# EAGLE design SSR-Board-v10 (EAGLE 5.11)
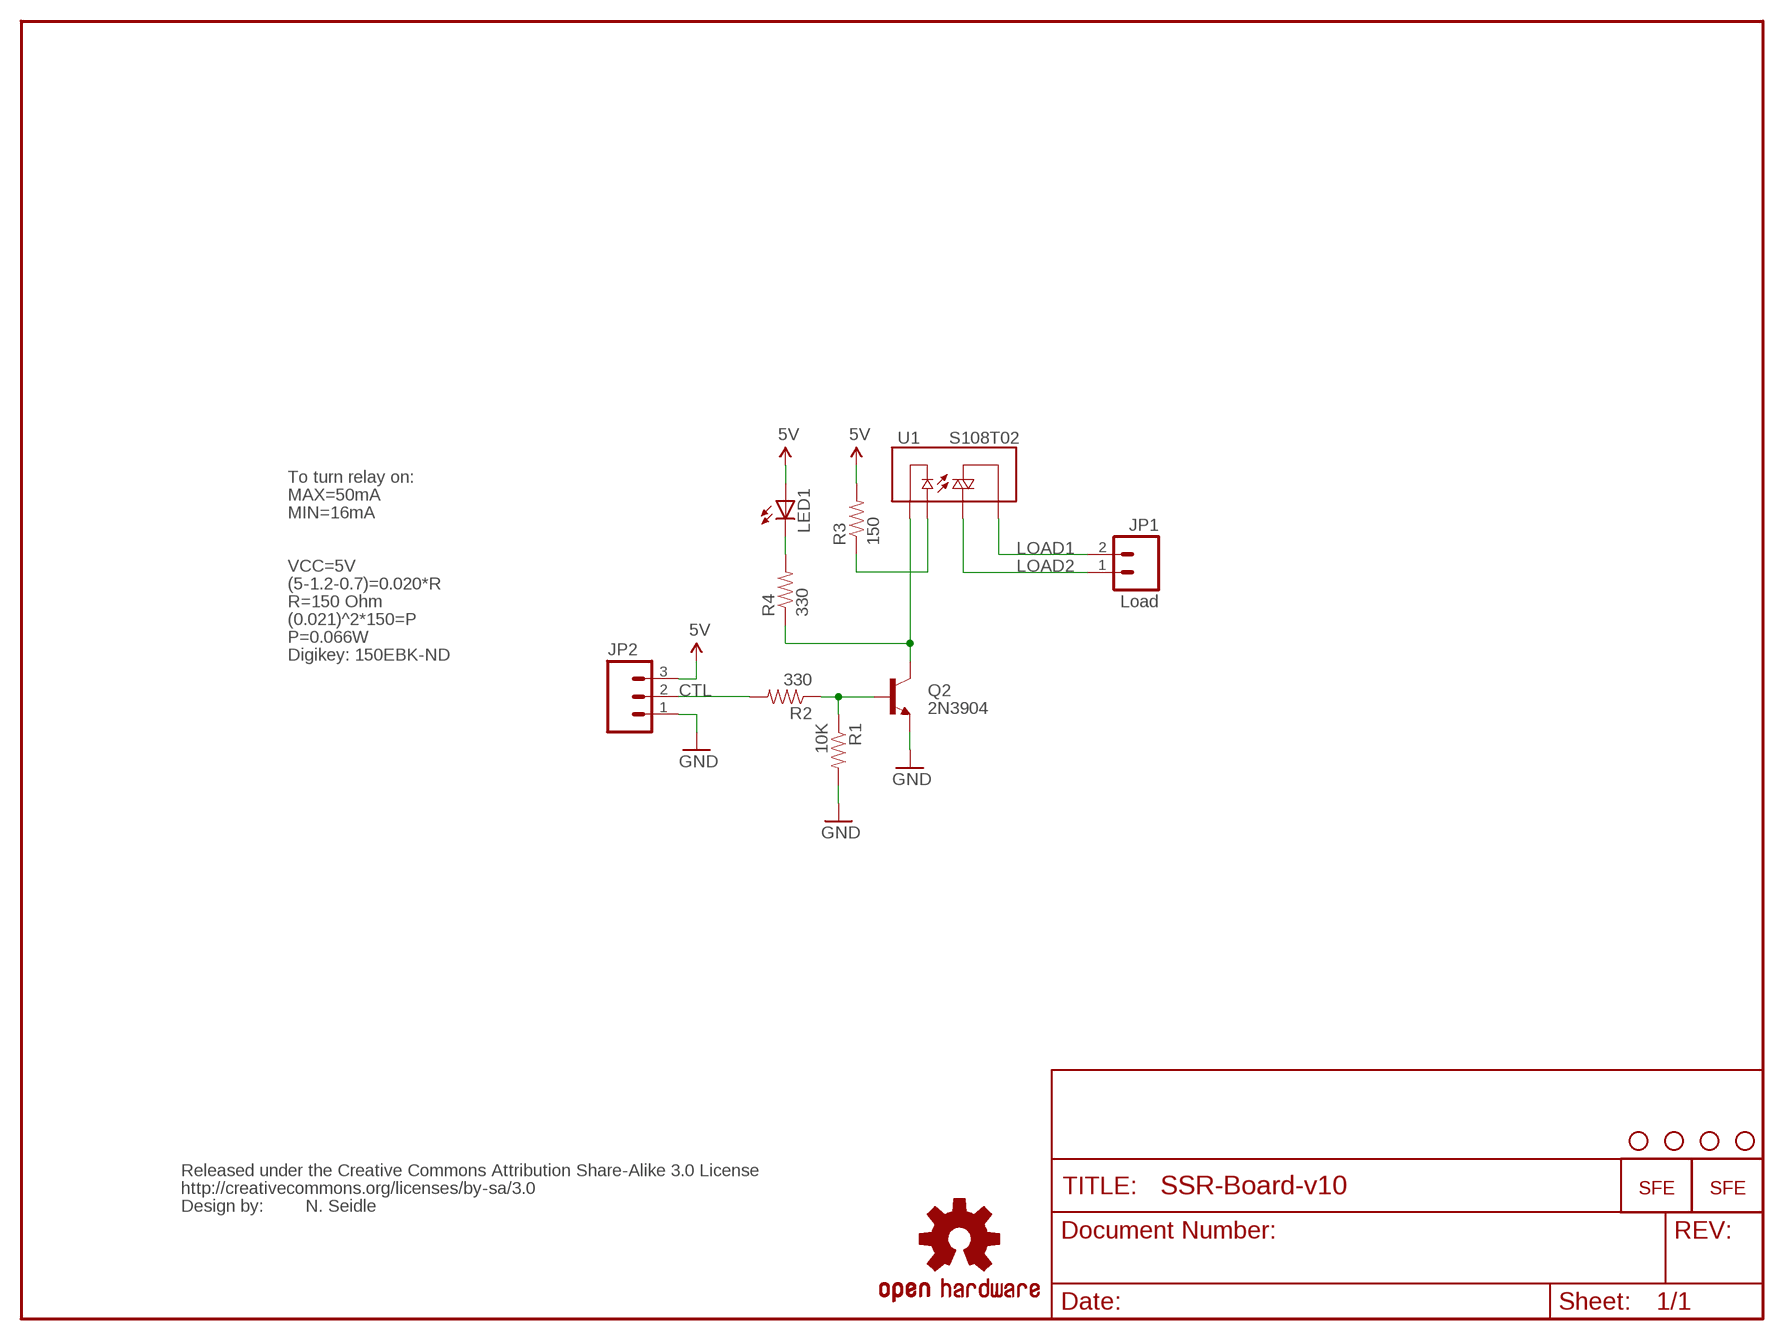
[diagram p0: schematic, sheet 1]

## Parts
JP1  Load  M025MM  [SCREWTERMINAL-5MM-2]
JP2  M03SCREW  [SCREWTERMINAL-3.5MM-3]
JP3  LOGO-SFESK  [SFE-LOGO-FLAME]
LED1  LED5MM  [LED5MM]
Q2  2N3904  TRANSISTOR_NPNTO92  [TO-92]
R1  10K  RESISTORAXIAL-0.3  [AXIAL-0.3]
R2  330  RESISTORAXIAL-0.3  [AXIAL-0.3]
R3  150  RESISTORAXIAL-0.3  [AXIAL-0.3]
R4  330  RESISTORAXIAL-0.3  [AXIAL-0.3]
U1  S108T02  RELAY-SOLIDSTATEPTH  [RELAY-S108T02]
U$1  LOGO-SFENEW  [SFE-NEW-WEBLOGO]
U$2  OSHW-LOGO  OSHW-LOGOS  [OSHW-LOGO-S]
U$3  STAND-OFF  [STAND-OFF]
U$4  STAND-OFF  [STAND-OFF]
U$5  STAND-OFF  [STAND-OFF]
U$7  STAND-OFF  [STAND-OFF]
U$9  CREATIVE_COMMONS  [CREATIVE_COMMONS]

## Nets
5V: JP2.3 LED1.A R3.P$2
COIL: Q2.3(C) R4.P$1 U1.4(-)
CTL: JP2.2 R2.P$2
GND: JP2.1 Q2.1(E) R1.P$2
LOAD1: JP1.2 U1.1(T1)
LOAD2: JP1.1 U1.2(T2)
N$1: R3.P$1 U1.3(+)
N$6: Q2.2(B) R1.P$1 R2.P$1
N$9: LED1.K(C) R4.P$2

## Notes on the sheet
- To turn relay on:
- MAX=50mA
- MIN=16mA
- VCC=5V
- (5-1.2-0.7)=0.020*R
- R=150 Ohm
- (0.021)^2*150=P
- P=0.066W
- Digikey: 150EBK-ND
- N. Seidle

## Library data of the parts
JP1 = SparkFun:M02: Header 2
JP2 = SparkFun:M03: Header 3 Standard 3-pin 0.1" header. Use with straight break away headers (SKU : PRT-00116), right angle break away headers (PRT-00553), swiss pins (PRT-00743), machine pins (PRT-00117), and female headers (PRT-00115). Molex polarized connector foot print use with SKU : PRT-08232 with associated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
JP3 U$1 = SparkFun:LOGO-SFE: Spark Fun Electronics PCB Logo
LED1 = SparkFun:LED: LEDs
Q2 = SparkFun:TRANSISTOR_NPN: Transistor NPN BJT configuration in SOT23 package. MMBT2222 is the common NPN we use. Double check BCE configuration again layout.
R1-R4 = SparkFun:RESISTOR: Resistor
U1 = SparkFun:RELAY-SOLIDSTATE
U$2 = SparkFun:OSHW-LOGO: Open Source Hardware Logo This logo indicates the piece of hardware it is found on incorporates a OSHW license and/or adheres to the definition of open source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
U$3-U$5 U$7 = SparkFun:STAND-OFF: Stand Off
U$9 = SparkFun:CREATIVE_COMMONS

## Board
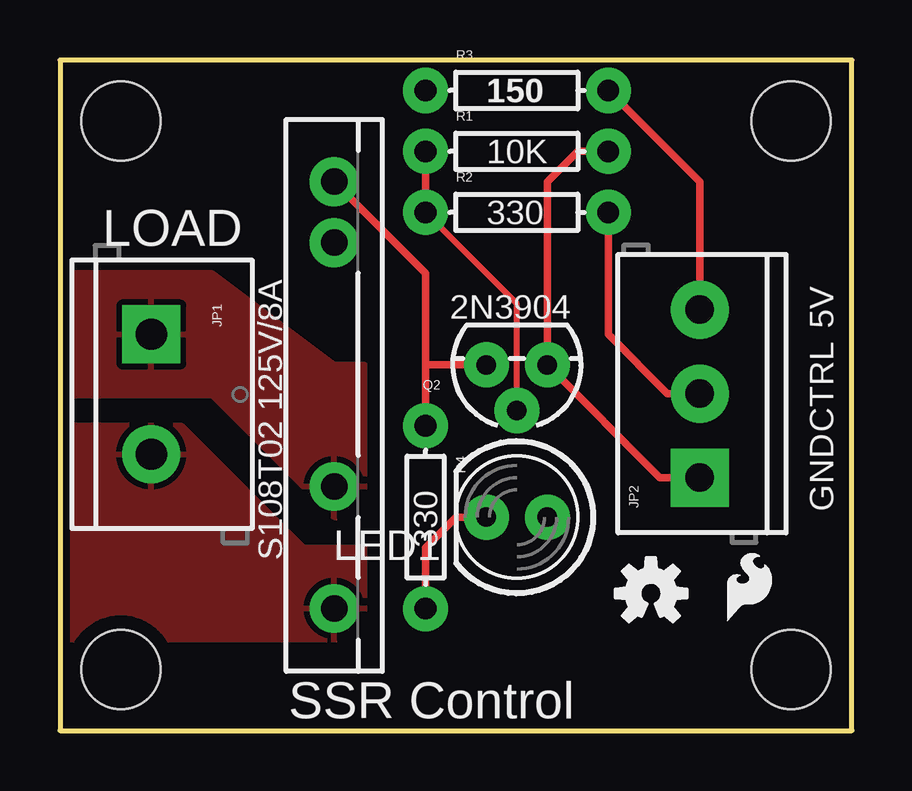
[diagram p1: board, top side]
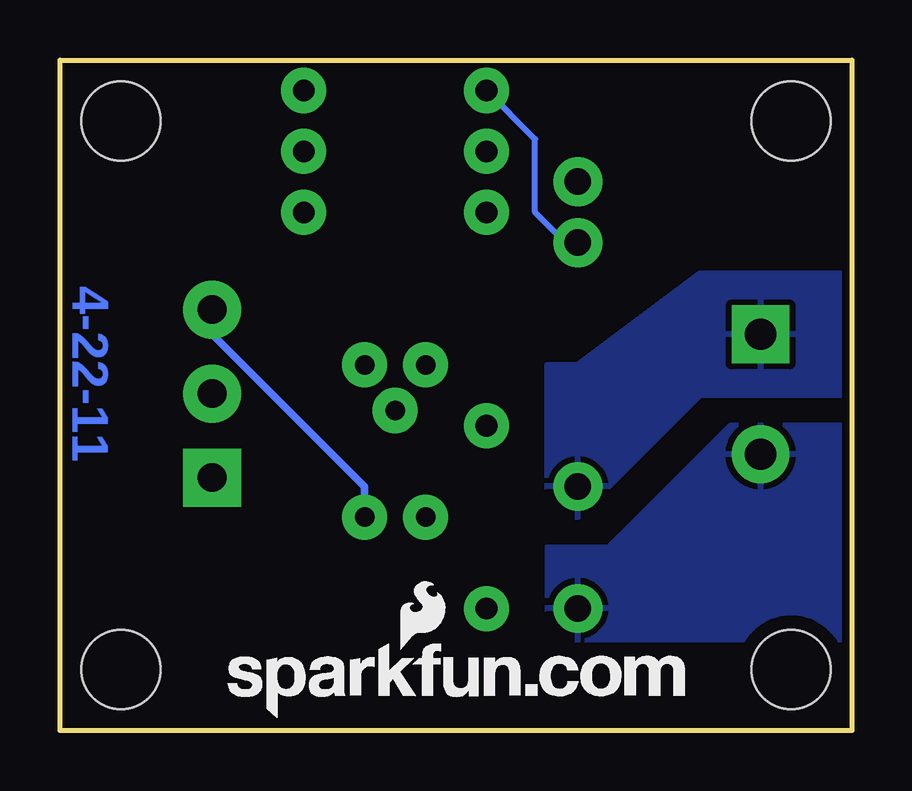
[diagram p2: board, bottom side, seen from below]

Size 33.02 x 27.94 mm. Coordinates in mm from the lower left corner, seen from the top.
Outline: 0,0 33.02,0 33.02,27.94 0,27.94 0,0
Copper layers (1*16): Top 0.035mm / dielectric 1.5mm / Bottom 0.035mm
Design rules "SparkFun *": minimum track width 10mil, minimum drill 20mil, track to track 8mil, track to pad 8mil, pad to pad 8mil, via to via 8mil, smd to smd 8mil, copper to edge 10mil, drill to drill 8mil, minimum pad ring 12mil, minimum via ring 10mil, stop-mask expansion 4mil, vias tented up to drill 20mil, thermal gap 10mil

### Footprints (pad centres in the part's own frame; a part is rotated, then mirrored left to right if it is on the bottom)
SCREWTERMINAL-5MM-2 = drill 1.3 pad 2.413 square: 1 0,0 | drill 1.3 pad 2.413 round: 2 5,0
SCREWTERMINAL-3.5MM-3 = drill 1.2 pad 2.413 square: 1 0,0 | drill 1.2 pad 2.413 round: 2 3.5,0; 3 7,0
LED5MM = drill 0.813 pad 1.88 round: A -1.27,0; K 1.27,0
TO-92 = drill 0.813 pad 1.88 round: 1 -1.27,0; 2 0,1.905; 3 1.27,0
AXIAL-0.3 = drill 0.9 pad 1.88 round: P$1 -3.81,0; P$2 3.81,0
RELAY-S108T02 = drill 1.1 pad 2.032 round: 1 -8.88,0; 2 -3.8,0; 3 6.36,0; 4 8.9,0
STAND-OFF = hole 3.302: 0,0

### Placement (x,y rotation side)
JP1  3.81,16.51 270 top
JP2  26.67,10.54 90 top
JP3  27.81,4.57 0 top
LED1  19.05,8.89 180 top
Q2  19.05,15.24 180 top
R1  19.05,24.13 0 top
R2  19.05,21.59 0 top
R3  19.05,26.67 0 top
R4  15.24,8.89 270 top
U1  11.43,13.97 90 top
U$1  26.04,0.51 0 bottom
U$2  24.64,5.71 0 top
U$3  2.54,2.54 0 top
U$4  30.48,2.54 0 top
U$5  30.48,25.4 0 top
U$7  2.54,25.4 0 top
U$9  not placed on the board

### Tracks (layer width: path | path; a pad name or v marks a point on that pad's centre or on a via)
5V
  Top 0.305: JP2.3 26.67,22.86 R3.P$2
  Bottom 0.305: JP2.3 26.67,16.51 20.32,10.16 LED1.A
COIL
  Top 0.305: R4.P$1 15.24,15.24 | 15.24,15.24 15.24,19.05 U1.4 | 15.24,15.24 Q2.3
CTL
  Top 0.305: JP2.2 25.33,14.04 22.86,16.51 R2.P$2
GND
  Top 0.305: R1.P$2 21.59,24.13 20.32,22.86 Q2.1 25.02,10.54 JP2.1
LOAD1
  pour Bottom (isolate 0.305): 0,12.7 5.08,12.7 10.16,7.62 12.7,7.62 12.7,3.81 0,3.81
  pour Top (isolate 0.305): 0,3.81 12.7,3.81 12.7,7.62 10.16,7.62 5.08,12.7 0,12.7
LOAD2
  pour Bottom (isolate 0.305): 0,13.97 6.35,13.97 11.43,8.89 12.7,8.89 12.7,15.24 11.43,15.24 6.35,19.05 0,19.05
  pour Top (isolate 0.305): 0,13.97 6.35,13.97 11.43,8.89 12.7,8.89 12.7,15.24 11.43,15.24 6.35,19.05 0,19.05
N$1
  Bottom 0.254: U1.3 11.95,20.33 13.21,21.59 13.21,24.64 R3.P$1
N$6
  Top 0.254: Q2.2 19.05,17.78 R2.P$1
  Top 0.305: R2.P$1 R1.P$1
N$9
  Top 0.305: R4.P$2 15.24,7.62 16.51,8.89 LED1.K

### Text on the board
Bottom: 4-22-11
tPlace: LOAD | 5V | CTRL | GND | S108T02 125V/8A | SSR Control | N. Seidle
